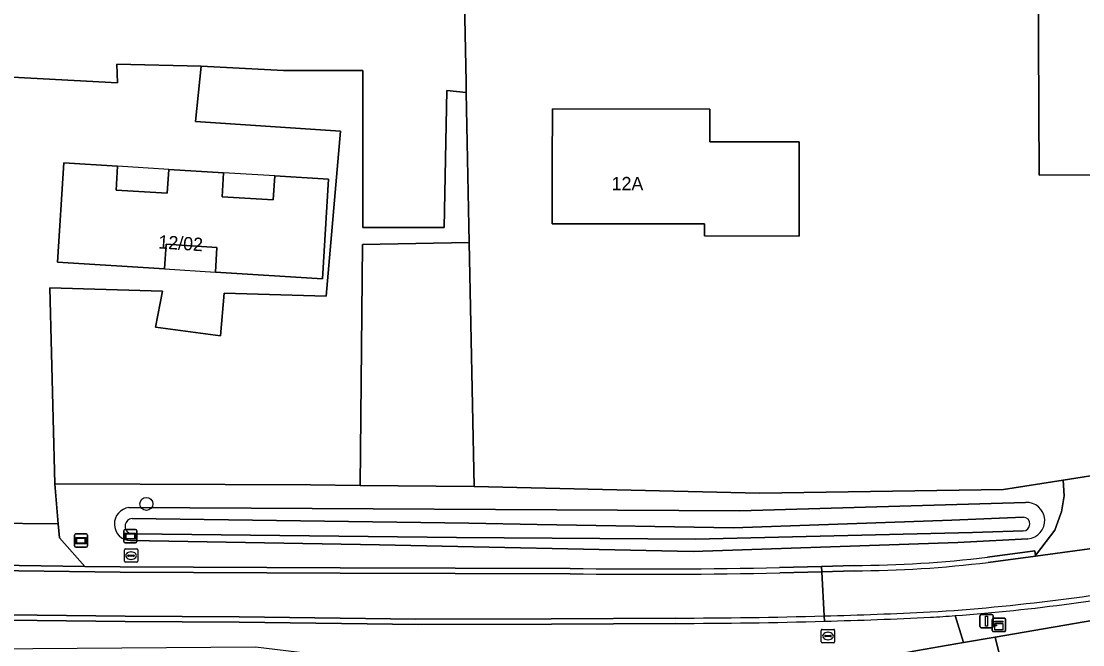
# Model space of a CAD drawing. Extents: x 162510 to 163918, y 388494 to 389774.
# Drawn here: x 163019.4 to 163099.2, y 388963.9 to 389010.7 of the extents above; entities that cross this region are included whole.
import ezdxf

# ---------------------------------------------------------------- set-up
doc = ezdxf.new("R2010")
doc.units = 0
for name, color, linetype in [('IMGEO_Boom', 7, 'Continuous'), ('IMGEO_Brandkraan', 7, 'Continuous'), ('IMGEO_Erf', 7, 'Continuous'), ('IMGEO_Grasland_agrarisch', 7, 'Continuous'), ('IMGEO_Grasland_overig', 7, 'Continuous'), ('IMGEO_Groenvoorziening', 7, 'Continuous'), ('IMGEO_Informatiebord', 7, 'Continuous'), ('IMGEO_Kast', 7, 'Continuous'), ('IMGEO_Lichtmast', 7, 'Continuous'), ('IMGEO_Oever', 7, 'Continuous'), ('IMGEO_Pand', 7, 'Continuous'), ('IMGEO_Pand_nummerreeks', 7, 'Continuous'), ('IMGEO_Pand_overbouw', 7, 'Continuous'), ('IMGEO_Rijbaan_lokaal_gesloten', 7, 'Continuous'), ('IMGEO_Rijbaan_lokaal_halfverhard', 7, 'Continuous'), ('IMGEO_Rijbaan_lokaal_open', 7, 'Continuous'), ('IMGEO_Rioolput', 7, 'Continuous'), ('IMGEO_Verklikker', 7, 'Continuous'), ('IMGEO_Waterloop', 7, 'Continuous')]:
    doc.layers.add(name, color=color, linetype=linetype)

msp = doc.modelspace()

# ---------------------------------------------------------------- linework, layer by layer
at = {"layer": 'IMGEO_Boom'}
msp.add_circle((163028.841, 388974.468), 0.489, dxfattribs=at)
at = {"layer": 'IMGEO_Brandkraan'}
for p, q in [((163027.189, 388970.161), (163027.189, 388971.013)), ((163027.264, 388971.087), (163028.116, 388971.087)), ((163027.448, 388970.581), (163027.448, 388970.593)), ((163027.886, 388970.544), (163027.488, 388970.544)), ((163027.491, 388970.63), (163027.889, 388970.63)), ((163027.677, 388970.867), (163027.702, 388970.867)), ((163027.932, 388970.593), (163027.932, 388970.581)), ((163028.19, 388971.013), (163028.19, 388970.161)), ((163028.116, 388970.087), (163027.264, 388970.087)), ((163027.7, 388970.307), (163027.675, 388970.307))]:
    msp.add_line(p, q, dxfattribs=at)
for points in [[(163027.189, 388970.161), (163027.189, 388971.013)], [(163027.264, 388971.087), (163028.116, 388971.087)], [(163028.19, 388971.013), (163028.19, 388970.161)], [(163028.116, 388970.087), (163027.264, 388970.087)]]:
    msp.add_lwpolyline(points, dxfattribs=at)
for centre, radius, start, end in [((163027.266, 388971.011), 0.0765, 91.55205, 178.44795), ((163027.266, 388971.011), 0.0765, 91.55205, 178.44795), ((163027.488, 388970.59), 0.0403, 85.87752, 175.75265), ((163027.485, 388970.58), 0.0366, 178.93798, 274.71019), ((163027.889, 388970.587), 0.043, 264.86636, 352.45326), ((163027.893, 388970.592), 0.0386, 1.73085, 96.63898), ((163028.114, 388971.011), 0.0765, 1.55205, 88.44795), ((163028.114, 388971.011), 0.0765, 1.55205, 88.44795), ((163027.266, 388970.163), 0.0765, 181.55205, 268.44795), ((163027.266, 388970.163), 0.0765, 181.55205, 268.44795), ((163028.114, 388970.163), 0.0765, 271.55205, 358.44795), ((163028.114, 388970.163), 0.0765, 271.55205, 358.44795)]:
    msp.add_arc(centre, radius, start, end, dxfattribs=at)
for centre, major_axis, ratio, start_param, end_param in [((163027.676, 388970.587), (-0.387, 0.002), 0.722429, 4.712389, 7.853982), ((163027.701, 388970.587), (-0.39, 0.002), 0.717154, 1.570796, 4.712389)]:
    msp.add_ellipse(centre, major_axis=major_axis, ratio=ratio, start_param=start_param, end_param=end_param, dxfattribs=at)
at = {"layer": 'IMGEO_Erf'}
for points in [[(163052.563, 389020.587), (163052.851, 389006.121), (163052.866, 389005.347), (163053.09, 388994.093), (163053.454, 388975.765), (163074.891, 388975.272), (163093.207, 388975.56), (163097.673, 388976.261), (163101.17, 388976.81), (163107.335, 388977.778), (163118.731, 388980.29), (163115.27, 389047.574)], [(163021.582, 388990.676), (163030.058, 388990.428), (163029.524, 388987.735), (163034.419, 388987.074), (163034.692, 388990.292), (163042.333, 388990.068), (163043.413, 389002.448), (163032.539, 389003.168), (163032.96, 389007.333), (163026.616, 389007.468), (163026.664, 389006.076), (163010.383, 389006.948), (163015.346, 388973.525), (163015.826, 388973.525)], [(163016.52, 388973.037), (163016.852, 388973.034), (163022.225, 388972.97), (163021.967, 388975.964), (163021.582, 388990.676)]]:
    msp.add_lwpolyline(points, dxfattribs=at)
for points in [[(163095.881, 388999.142), (163095.686, 389039.216), (163107.726, 389039.275), (163107.921, 388999.201)], [(163021.967, 388975.964), (163041.156, 388975.89), (163044.898, 388975.852), (163045.082, 388993.934), (163053.09, 388994.093), (163052.866, 389005.347), (163051.392, 389005.507), (163051.194, 388995.212), (163045.095, 388995.212), (163045.095, 389007.003), (163039.138, 389007.008), (163032.96, 389007.333), (163032.539, 389003.168), (163043.413, 389002.448), (163042.333, 388990.068), (163034.692, 388990.292), (163034.419, 388987.074), (163029.524, 388987.735), (163030.058, 388990.428), (163021.582, 388990.676)], [(163077.849, 388994.569), (163070.758, 388994.578), (163070.759, 388995.485), (163059.32, 388995.498), (163059.325, 389000), (163059.33, 389004.11), (163071.149, 389004.096), (163071.146, 389001.646), (163077.858, 389001.639), (163077.856, 389000)], [(163022.631, 389000.069), (163026.673, 388999.819), (163026.562, 388998.022), (163030.405, 388997.785), (163030.516, 388999.581), (163034.64, 388999.326), (163034.529, 388997.529), (163038.371, 388997.292), (163038.483, 388999.088), (163042.525, 388998.838), (163042.062, 388991.372), (163034.027, 388991.869), (163034.142, 388993.716), (163030.318, 388993.952), (163030.204, 388992.106), (163022.169, 388992.603)], [(163130.634, 388947.318), (163130.113, 388950.183), (163126.78, 388949.576), (163125.622, 388956.459), (163126.1, 388968.984), (163125.918, 388970.212), (163122.893, 388969.691), (163118.423, 388968.921), (163092.585, 388964.47), (163103.049, 388922.376), (163103.547, 388920.178), (163110.429, 388922.204), (163117.794, 388923.892), (163119.326, 388918.852), (163128.061, 388921.054), (163125.484, 388932.995), (163133.459, 388934.716), (163141.553, 388934.877), (163140.769, 388939.653), (163139.523, 388941.721), (163131.905, 388940.334)]]:
    msp.add_lwpolyline(points, close=True, dxfattribs=at)
at = {"layer": 'IMGEO_Grasland_agrarisch'}
for points in [[(163010.383, 389006.948), (163026.664, 389006.076), (163026.616, 389007.468), (163032.96, 389007.333), (163039.138, 389007.008), (163045.095, 389007.003), (163045.095, 388995.212), (163051.194, 388995.212), (163051.392, 389005.507), (163052.866, 389005.347), (163052.851, 389006.121), (163052.563, 389020.587)], [(163103.049, 388922.376), (163092.585, 388964.47), (163090.188, 388964.057), (163086.751, 388963.465), (163082.659, 388962.692), (163076.92, 388962.425), (163068.888, 388962.174), (163059.41, 388962.047), (163052.955, 388961.925), (163054.44, 388908.441)]]:
    msp.add_lwpolyline(points, dxfattribs=at)
at = {"layer": 'IMGEO_Grasland_overig'}
for points in [[(163097.756, 388975.067), (163097.673, 388976.261), (163093.207, 388975.56), (163074.891, 388975.272), (163053.454, 388975.765), (163044.898, 388975.852), (163041.156, 388975.89), (163021.967, 388975.964), (163022.225, 388972.97), (163022.314, 388971.933), (163024.225, 388969.778), (163026.883, 388969.744), (163043.397, 388969.679), (163060.659, 388969.621)], [(163027.529, 388974.202), (163073.394, 388973.951), (163094.858, 388974.582)], [(163092.011, 388970.475), (163095.562, 388970.939), (163095.607, 388970.596), (163095.679, 388970.691), (163097.048, 388972.504), (163097.514, 388973.745), (163097.56, 388973.869), (163097.756, 388975.067)], [(163095.028, 388971.85), (163089.781, 388971.573), (163069.902, 388970.896), (163046.354, 388971.384), (163027.654, 388971.713)], [(163076.39, 388969.696), (163079.544, 388969.781), (163081.98, 388969.846)], [(163089.586, 388966.085), (163090.188, 388964.057), (163092.585, 388964.47), (163118.423, 388968.921)], [(163068.575, 388965.498), (163059.251, 388965.446), (163049.249, 388965.428), (163035.814, 388965.597), (163027.249, 388965.634), (163018.442, 388965.738), (163012.75, 388965.872), (163005.306, 388966.012), (163005.318, 388966.412), (163004.846, 388966.436)], [(163002.071, 388963.522), (163002.495, 388963.475), (163016.933, 388963.586), (163037.03, 388963.741), (163052.129, 388961.909), (163052.955, 388961.925), (163059.41, 388962.047), (163068.888, 388962.174), (163076.92, 388962.425), (163082.659, 388962.692), (163086.751, 388963.465), (163090.188, 388964.057), (163089.586, 388966.085)]]:
    msp.add_lwpolyline(points, dxfattribs=at)
for centre, radius, start, end in [((163094.929, 388973.215), 1.369, 274.1422, 92.97913), ((163027.686, 388972.962), 1.25, 97.19933, 181.36812), ((163027.687, 388972.964), 1.251, 181.44667, 268.50631), ((163081.621, 389055.864), 86.019, 270.23887, 276.93727), ((163066.398, 389415.719), 446.135, 269.26296, 271.28337), ((163077.903, 389121.3), 155.654, 274.30444, 280.7547), ((163068.006, 389387.863), 422.365, 270.07716, 271.59372), ((163067.874, 389393.864), 428.368, 271.58905, 272.65474), ((163076.356, 389144.342), 178.748, 273.64356, 274.24471)]:
    msp.add_arc(centre, radius, start, end, dxfattribs=at)
at = {"layer": 'IMGEO_Groenvoorziening'}
msp.add_lwpolyline([(163053.09, 388994.093), (163045.082, 388993.934), (163044.898, 388975.852), (163053.454, 388975.765)], close=True, dxfattribs=at)
at = {"layer": 'IMGEO_Informatiebord'}
for p, q in [((163023.432, 388971.313), (163023.432, 388972.113)), ((163023.432, 388972.113), (163023.432, 388971.313)), ((163023.532, 388972.213), (163024.322, 388972.213)), ((163024.322, 388972.213), (163023.532, 388972.213)), ((163024.422, 388972.113), (163024.422, 388971.313)), ((163024.422, 388971.313), (163024.422, 388972.113)), ((163024.322, 388971.213), (163023.532, 388971.213)), ((163023.532, 388971.213), (163024.322, 388971.213))]:
    msp.add_line(p, q, dxfattribs=at)
for points in [[(163023.533, 388971.945), (163024.321, 388971.945), (163024.321, 388971.481), (163023.533, 388971.481), (163023.533, 388971.945)], [(163023.598, 388971.88), (163023.598, 388971.546), (163024.256, 388971.546), (163024.256, 388971.88), (163023.598, 388971.88)]]:
    msp.add_lwpolyline(points, dxfattribs=at)
for centre, start, end in [((163023.532, 388972.113), 90, 180), ((163023.532, 388972.113), 90, 180), ((163024.322, 388972.113), 0, 90), ((163024.322, 388972.113), 360, 90), ((163023.532, 388971.313), 180, 270), ((163023.532, 388971.313), 180, 270), ((163024.322, 388971.313), 270, 0), ((163024.322, 388971.313), 270, 0)]:
    msp.add_arc(centre, 0.1, start, end, dxfattribs=at)
at = {"layer": 'IMGEO_Kast'}
for p, q in [((163092.362, 388964.961), (163092.362, 388965.802)), ((163092.362, 388965.802), (163092.362, 388964.961)), ((163092.437, 388965.886), (163093.278, 388965.886)), ((163093.278, 388965.886), (163092.437, 388965.886)), ((163093.362, 388965.811), (163093.362, 388964.97)), ((163093.362, 388964.97), (163093.362, 388965.811)), ((163093.287, 388964.886), (163092.446, 388964.886)), ((163092.446, 388964.886), (163093.287, 388964.886))]:
    msp.add_line(p, q, dxfattribs=at)
for points in [[(163092.557, 388965.676), (163093.157, 388965.676), (163093.157, 388965.591), (163092.557, 388965.591), (163092.557, 388965.676)], [(163092.557, 388965.501), (163093.157, 388965.501), (163093.157, 388965.012), (163092.557, 388965.012), (163092.557, 388965.501)]]:
    msp.add_lwpolyline(points, dxfattribs=at)
msp.add_circle((163092.641, 388965.35), 0.0377, dxfattribs=at)
for centre, start, end in [((163092.44, 388965.808), 92.4484, 184.28452), ((163092.44, 388965.808), 92.4484, 184.28452), ((163093.284, 388965.808), 2.4484, 94.28452), ((163093.284, 388965.808), 2.4484, 94.28452), ((163092.44, 388964.964), 182.4484, 274.28452), ((163092.44, 388964.964), 182.4484, 274.28452), ((163093.284, 388964.964), 272.4484, 4.28452), ((163093.284, 388964.964), 272.4484, 4.28452)]:
    msp.add_arc(centre, 0.0779, start, end, dxfattribs=at)
at = {"layer": 'IMGEO_Lichtmast'}
for p, q in [((163091.436, 388965.264), (163091.436, 388966.064)), ((163091.436, 388966.064), (163091.436, 388965.264)), ((163091.536, 388966.164), (163092.326, 388966.164)), ((163092.326, 388966.164), (163091.536, 388966.164)), ((163092.426, 388966.064), (163092.426, 388965.264)), ((163092.426, 388965.264), (163092.426, 388966.064)), ((163092.326, 388965.164), (163091.536, 388965.164)), ((163091.536, 388965.164), (163092.326, 388965.164))]:
    msp.add_line(p, q, dxfattribs=at)
msp.add_lwpolyline([(163091.856, 388966.039), (163092.006, 388966.039), (163092.006, 388965.289), (163091.856, 388965.289), (163091.856, 388966.039)], dxfattribs=at)
for centre, start, end in [((163091.536, 388966.064), 90, 180), ((163091.536, 388966.064), 90, 180), ((163092.326, 388966.064), 0, 90), ((163092.326, 388966.064), 360, 90), ((163091.536, 388965.264), 180, 270), ((163091.536, 388965.264), 180, 270), ((163092.326, 388965.264), 270, 0), ((163092.326, 388965.264), 270, 0)]:
    msp.add_arc(centre, 0.1, start, end, dxfattribs=at)
at = {"layer": 'IMGEO_Oever'}
for points in [[(163094.858, 388974.582), (163073.394, 388973.951), (163027.529, 388974.202)], [(163027.764, 388973.364), (163053.063, 388973.032), (163058.176, 388972.929), (163072.92, 388972.662), (163089.326, 388973.258)], [(163089.326, 388973.258), (163094.699, 388973.477)], [(163094.679, 388972.44), (163090.88, 388972.322), (163070.065, 388971.82), (163052.139, 388971.943), (163027.815, 388972.225)], [(163027.654, 388971.713), (163046.354, 388971.384), (163069.902, 388970.896), (163089.781, 388971.573), (163095.028, 388971.85)]]:
    msp.add_lwpolyline(points, dxfattribs=at)
for centre, radius, start, end in [((163094.929, 388973.215), 1.369, 274.1422, 92.97913), ((163027.686, 388972.962), 1.25, 97.19933, 181.36812), ((163027.687, 388972.964), 1.251, 181.44667, 268.50631), ((163027.81, 388972.795), 0.57, 168.20481, 270.54662), ((163027.811, 388972.795), 0.571, 94.71954, 168.28306), ((163094.666, 388972.959), 0.519, 271.4295, 86.36072)]:
    msp.add_arc(centre, radius, start, end, dxfattribs=at)
at = {"layer": 'IMGEO_Pand'}
for points in [[(163095.881, 388999.142), (163107.921, 388999.201), (163107.726, 389039.275), (163095.686, 389039.216)], [(163077.849, 388994.569), (163077.856, 389000), (163077.858, 389001.639), (163071.146, 389001.646), (163071.149, 389004.096), (163059.33, 389004.11), (163059.325, 389000), (163059.32, 388995.498), (163070.759, 388995.485), (163070.758, 388994.578)], [(163042.525, 388998.838), (163038.483, 388999.088), (163038.371, 388997.292), (163034.529, 388997.529), (163034.64, 388999.326), (163030.516, 388999.581), (163030.405, 388997.785), (163026.562, 388998.022), (163026.673, 388999.819), (163022.631, 389000.069), (163022.169, 388992.603), (163030.204, 388992.106), (163030.318, 388993.952), (163034.142, 388993.716), (163034.027, 388991.869), (163042.062, 388991.372)]]:
    msp.add_lwpolyline(points, close=True, dxfattribs=at)
at = {"layer": 'IMGEO_Pand_overbouw'}
for points in [[(163030.516, 388999.581), (163026.673, 388999.819), (163026.562, 388998.022), (163030.405, 388997.785)], [(163038.483, 388999.088), (163034.64, 388999.326), (163034.529, 388997.529), (163038.371, 388997.292)], [(163034.027, 388991.869), (163034.142, 388993.716), (163030.318, 388993.952), (163030.204, 388992.106)]]:
    msp.add_lwpolyline(points, close=True, dxfattribs=at)
at = {"layer": 'IMGEO_Rijbaan_lokaal_gesloten'}
for points in [[(163172.94, 388985.959), (163163.656, 388983.799), (163154.102, 388981.738), (163146.921, 388980.278), (163139.166, 388978.713), (163129.164, 388976.603), (163118.761, 388974.471), (163109.164, 388972.585), (163105.911, 388971.943), (163104.779, 388971.756), (163102.066, 388971.421), (163095.614, 388970.542), (163092.059, 388970.078)], [(163060.658, 388969.221), (163043.395, 388969.279), (163026.878, 388969.344), (163019.275, 388969.441), (163016.375, 388969.489), (163010.694, 388969.666), (163006.164, 388969.852), (163001.869, 388970.009), (162995.115, 388970.321), (162989.16, 388970.649), (162986.023, 388970.77), (162985.329, 388970.797), (162980.065, 388971.129), (162974.827, 388971.464), (162970.89, 388971.741), (162967.254, 388971.997), (162965.448, 388972.167), (162962.802, 388972.559), (162960.469, 388972.811), (162956.88, 388973.136), (162953.077, 388973.591)], [(162947.161, 388970.98), (162953.292, 388970.102), (162965.732, 388968.844), (162970.174, 388968.559), (162975.389, 388968.225), (162985.053, 388967.564), (162990.798, 388967.159), (162991.481, 388967.111), (163004.846, 388966.436), (163005.318, 388966.412), (163012.759, 388966.272), (163018.447, 388966.138), (163027.251, 388966.034), (163035.819, 388965.997), (163049.064, 388965.828), (163059.249, 388965.846), (163068.574, 388965.898)], [(163079.565, 388969.381), (163076.399, 388969.296)], [(163081.982, 388969.446), (163079.565, 388969.381), (163079.733, 388966.06)], [(163079.733, 388966.06), (163079.565, 388969.381)]]:
    msp.add_lwpolyline(points, dxfattribs=at)
for centre, radius, start, end in [((163081.622, 389055.84), 86.394, 270.23878, 276.93867), ((163066.4, 389415.969), 446.785, 269.26361, 271.28237), ((163077.92, 389121.179), 155.132, 273.61082, 280.75683), ((163067.867, 389399.007), 433.11, 270.09352, 271.56994), ((163067.846, 389394.154), 428.259, 271.59058, 272.65587)]:
    msp.add_arc(centre, radius, start, end, dxfattribs=at)
at = {"layer": 'IMGEO_Rijbaan_lokaal_halfverhard'}
for points in [[(163024.225, 388969.778), (163019.282, 388969.841), (163016.387, 388969.889), (163015.793, 388969.908), (163010.71, 388970.066), (163010.586, 388970.071), (163006.179, 388970.252), (163002.329, 388970.393), (163001.887, 388970.409), (162995.137, 388970.72), (162989.175, 388971.049), (162986.049, 388971.17), (162986.023, 388970.77), (162989.16, 388970.649), (162995.115, 388970.321), (163001.869, 388970.009), (163006.164, 388969.852), (163010.694, 388969.666), (163016.375, 388969.489), (163019.275, 388969.441), (163026.878, 388969.344), (163043.395, 388969.279), (163060.658, 388969.221)], [(163095.614, 388970.542), (163095.607, 388970.596), (163095.562, 388970.939), (163092.011, 388970.475)], [(163092.059, 388970.078), (163095.614, 388970.542)], [(163060.659, 388969.621), (163043.397, 388969.679), (163026.883, 388969.744), (163024.225, 388969.778)], [(163076.399, 388969.296), (163079.565, 388969.381), (163079.544, 388969.781), (163076.39, 388969.696)], [(163081.98, 388969.846), (163079.544, 388969.781), (163079.565, 388969.381), (163081.982, 388969.446)], [(163005.318, 388966.412), (163005.306, 388966.012), (163012.75, 388965.872), (163018.442, 388965.738), (163027.249, 388965.634), (163035.814, 388965.597), (163049.249, 388965.428), (163059.251, 388965.446), (163068.575, 388965.498)], [(163068.574, 388965.898), (163059.249, 388965.846), (163049.064, 388965.828), (163035.819, 388965.997), (163027.251, 388966.034), (163018.447, 388966.138), (163012.759, 388966.272), (163005.318, 388966.412)], [(163079.753, 388965.661), (163079.733, 388966.06)], [(163079.733, 388966.06), (163079.753, 388965.661)]]:
    msp.add_lwpolyline(points, dxfattribs=at)
for centre, radius, start, end in [((163081.621, 389055.864), 86.019, 270.23887, 276.93727), ((163066.398, 389415.719), 446.135, 269.26296, 271.28337), ((163081.622, 389055.84), 86.394, 270.23878, 276.93867), ((163066.4, 389415.969), 446.785, 269.26361, 271.28237), ((163077.92, 389121.179), 155.132, 273.61082, 280.75683), ((163077.903, 389121.3), 155.654, 274.30444, 280.7547), ((163067.867, 389399.007), 433.11, 270.09352, 271.56994), ((163068.006, 389387.863), 422.365, 270.07716, 271.59372), ((163067.846, 389394.154), 428.259, 271.59058, 272.65587), ((163067.874, 389393.864), 428.368, 271.58905, 272.65474), ((163076.356, 389144.342), 178.748, 273.64356, 274.24471)]:
    msp.add_arc(centre, radius, start, end, dxfattribs=at)
at = {"layer": 'IMGEO_Rijbaan_lokaal_open'}
for points in [[(163103.264, 388973.544), (163102.437, 388974.556), (163102.282, 388974.746), (163101.606, 388975.776), (163101.17, 388976.81), (163097.673, 388976.261), (163097.756, 388975.067), (163097.56, 388973.869), (163097.514, 388973.745), (163097.048, 388972.504), (163095.679, 388970.691), (163095.607, 388970.596), (163095.614, 388970.542), (163102.066, 388971.421), (163104.779, 388971.756), (163104.69, 388972.127), (163104.899, 388972.165)], [(163022.314, 388971.933), (163022.225, 388972.97), (163016.852, 388973.034), (163016.718, 388971.543), (163015.793, 388969.908), (163016.387, 388969.889), (163019.282, 388969.841), (163024.225, 388969.778)]]:
    msp.add_lwpolyline(points, close=True, dxfattribs=at)
at = {"layer": 'IMGEO_Rioolput'}
for p, q in [((163079.524, 388964.125), (163079.524, 388964.977)), ((163079.599, 388965.051), (163080.451, 388965.051)), ((163080.525, 388964.977), (163080.525, 388964.125)), ((163080.451, 388964.051), (163079.599, 388964.051)), ((163079.783, 388964.545), (163079.783, 388964.557)), ((163080.221, 388964.508), (163079.823, 388964.508)), ((163079.826, 388964.594), (163080.224, 388964.594)), ((163080.035, 388964.271), (163080.01, 388964.271)), ((163080.012, 388964.831), (163080.037, 388964.831)), ((163080.267, 388964.557), (163080.267, 388964.545))]:
    msp.add_line(p, q, dxfattribs=at)
for points in [[(163079.524, 388964.125), (163079.524, 388964.977)], [(163079.599, 388965.051), (163080.451, 388965.051)], [(163080.525, 388964.977), (163080.525, 388964.125)], [(163080.451, 388964.051), (163079.599, 388964.051)]]:
    msp.add_lwpolyline(points, dxfattribs=at)
for centre, radius, start, end in [((163079.601, 388964.975), 0.0765, 91.55205, 178.44795), ((163079.601, 388964.975), 0.0765, 91.55205, 178.44795), ((163080.449, 388964.975), 0.0765, 1.55205, 88.44795), ((163080.449, 388964.975), 0.0765, 1.55205, 88.44795), ((163079.601, 388964.127), 0.0765, 181.55205, 268.44795), ((163079.601, 388964.127), 0.0765, 181.55205, 268.44795), ((163079.823, 388964.554), 0.0403, 85.87752, 175.75265), ((163079.82, 388964.544), 0.0366, 178.93798, 274.71019), ((163080.224, 388964.551), 0.043, 264.86636, 352.45326), ((163080.228, 388964.556), 0.0386, 1.73085, 96.63898), ((163080.449, 388964.127), 0.0765, 271.55205, 358.44795), ((163080.449, 388964.127), 0.0765, 271.55205, 358.44795)]:
    msp.add_arc(centre, radius, start, end, dxfattribs=at)
for centre, major_axis, ratio, start_param, end_param in [((163080.011, 388964.551), (-0.387, 0.002), 0.722429, 4.712389, 7.853982), ((163080.036, 388964.551), (-0.39, 0.002), 0.717154, 1.570796, 4.712389)]:
    msp.add_ellipse(centre, major_axis=major_axis, ratio=ratio, start_param=start_param, end_param=end_param, dxfattribs=at)
at = {"layer": 'IMGEO_Verklikker'}
for p, q in [((163027.139, 388971.642), (163027.139, 388972.442)), ((163027.139, 388972.442), (163027.139, 388971.642)), ((163027.239, 388972.542), (163028.029, 388972.542)), ((163028.029, 388972.542), (163027.239, 388972.542)), ((163028.129, 388972.442), (163028.129, 388971.642)), ((163028.129, 388971.642), (163028.129, 388972.442)), ((163028.029, 388971.542), (163027.239, 388971.542)), ((163027.239, 388971.542), (163028.029, 388971.542))]:
    msp.add_line(p, q, dxfattribs=at)
for points in [[(163027.24, 388972.274), (163028.028, 388972.274), (163028.028, 388971.81), (163027.24, 388971.81), (163027.24, 388972.274)], [(163027.305, 388972.209), (163027.305, 388971.875), (163027.963, 388971.875), (163027.963, 388972.209), (163027.305, 388972.209)]]:
    msp.add_lwpolyline(points, dxfattribs=at)
for centre, start, end in [((163027.239, 388972.442), 90, 180), ((163027.239, 388972.442), 90, 180), ((163028.029, 388972.442), 0, 90), ((163028.029, 388972.442), 360, 90), ((163027.239, 388971.642), 180, 270), ((163027.239, 388971.642), 180, 270), ((163028.029, 388971.642), 270, 0), ((163028.029, 388971.642), 270, 0)]:
    msp.add_arc(centre, 0.1, start, end, dxfattribs=at)
at = {"layer": 'IMGEO_Waterloop'}
for points in [[(163094.699, 388973.477), (163089.326, 388973.258), (163072.92, 388972.662), (163058.176, 388972.929), (163053.063, 388973.032), (163027.764, 388973.364)], [(163027.815, 388972.225), (163052.139, 388971.943), (163070.065, 388971.82), (163090.88, 388972.322)], [(163090.88, 388972.322), (163094.679, 388972.44)]]:
    msp.add_lwpolyline(points, dxfattribs=at)
for centre, radius, start, end in [((163027.81, 388972.795), 0.57, 168.20481, 270.54662), ((163027.811, 388972.795), 0.571, 94.71954, 168.28306), ((163094.666, 388972.959), 0.519, 271.4295, 86.36072)]:
    msp.add_arc(centre, radius, start, end, dxfattribs=at)

# ---------------------------------------------------------------- texts
at = {"layer": 'IMGEO_Pand_nummerreeks'}
for s, rotation, p in [('12A', 359.93489, (163063.778, 388998.013)), ('12/02', 356.25859, (163029.719, 388993.647))]:
    msp.add_text(s, height=1, rotation=rotation, dxfattribs=at).set_placement(p)

doc.saveas('drawing.dxf')
